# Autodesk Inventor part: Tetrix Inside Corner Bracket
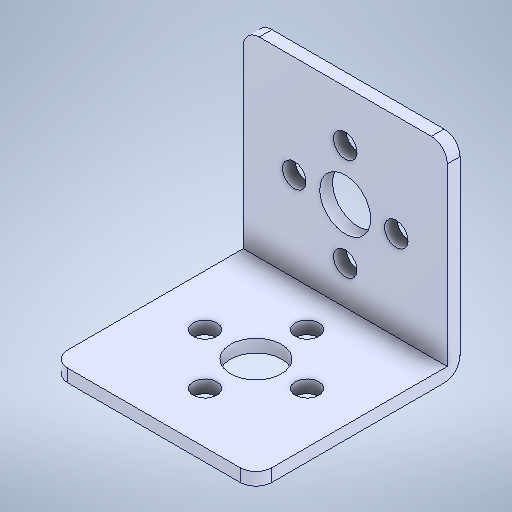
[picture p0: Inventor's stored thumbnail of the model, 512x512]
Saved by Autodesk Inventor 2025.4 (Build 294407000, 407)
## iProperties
Created: 2021-10
Part Number: Tetrix Inside Corner Bracket
Material: Genérico
Document SubType Name: Modeling
Designer: usuario
Density: 1 g/cm^3
Appearance: Valor por defecto
Author: usuario
Sending System: SolidWorks 2016
Last Author: LENOVO
Last Saved: 2021-10-23
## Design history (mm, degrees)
fillet "Fillet1"
node "Plane1"
node "Sólido1"
